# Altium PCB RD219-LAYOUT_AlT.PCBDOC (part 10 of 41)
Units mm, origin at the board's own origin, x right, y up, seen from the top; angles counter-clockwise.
Board outline 209.75 x 159.97 mm, 2 copper layers (TOP, BOTTOM), stack 0 mm thick; 398 components, 199 nets, 1469 pads, 0 vias.
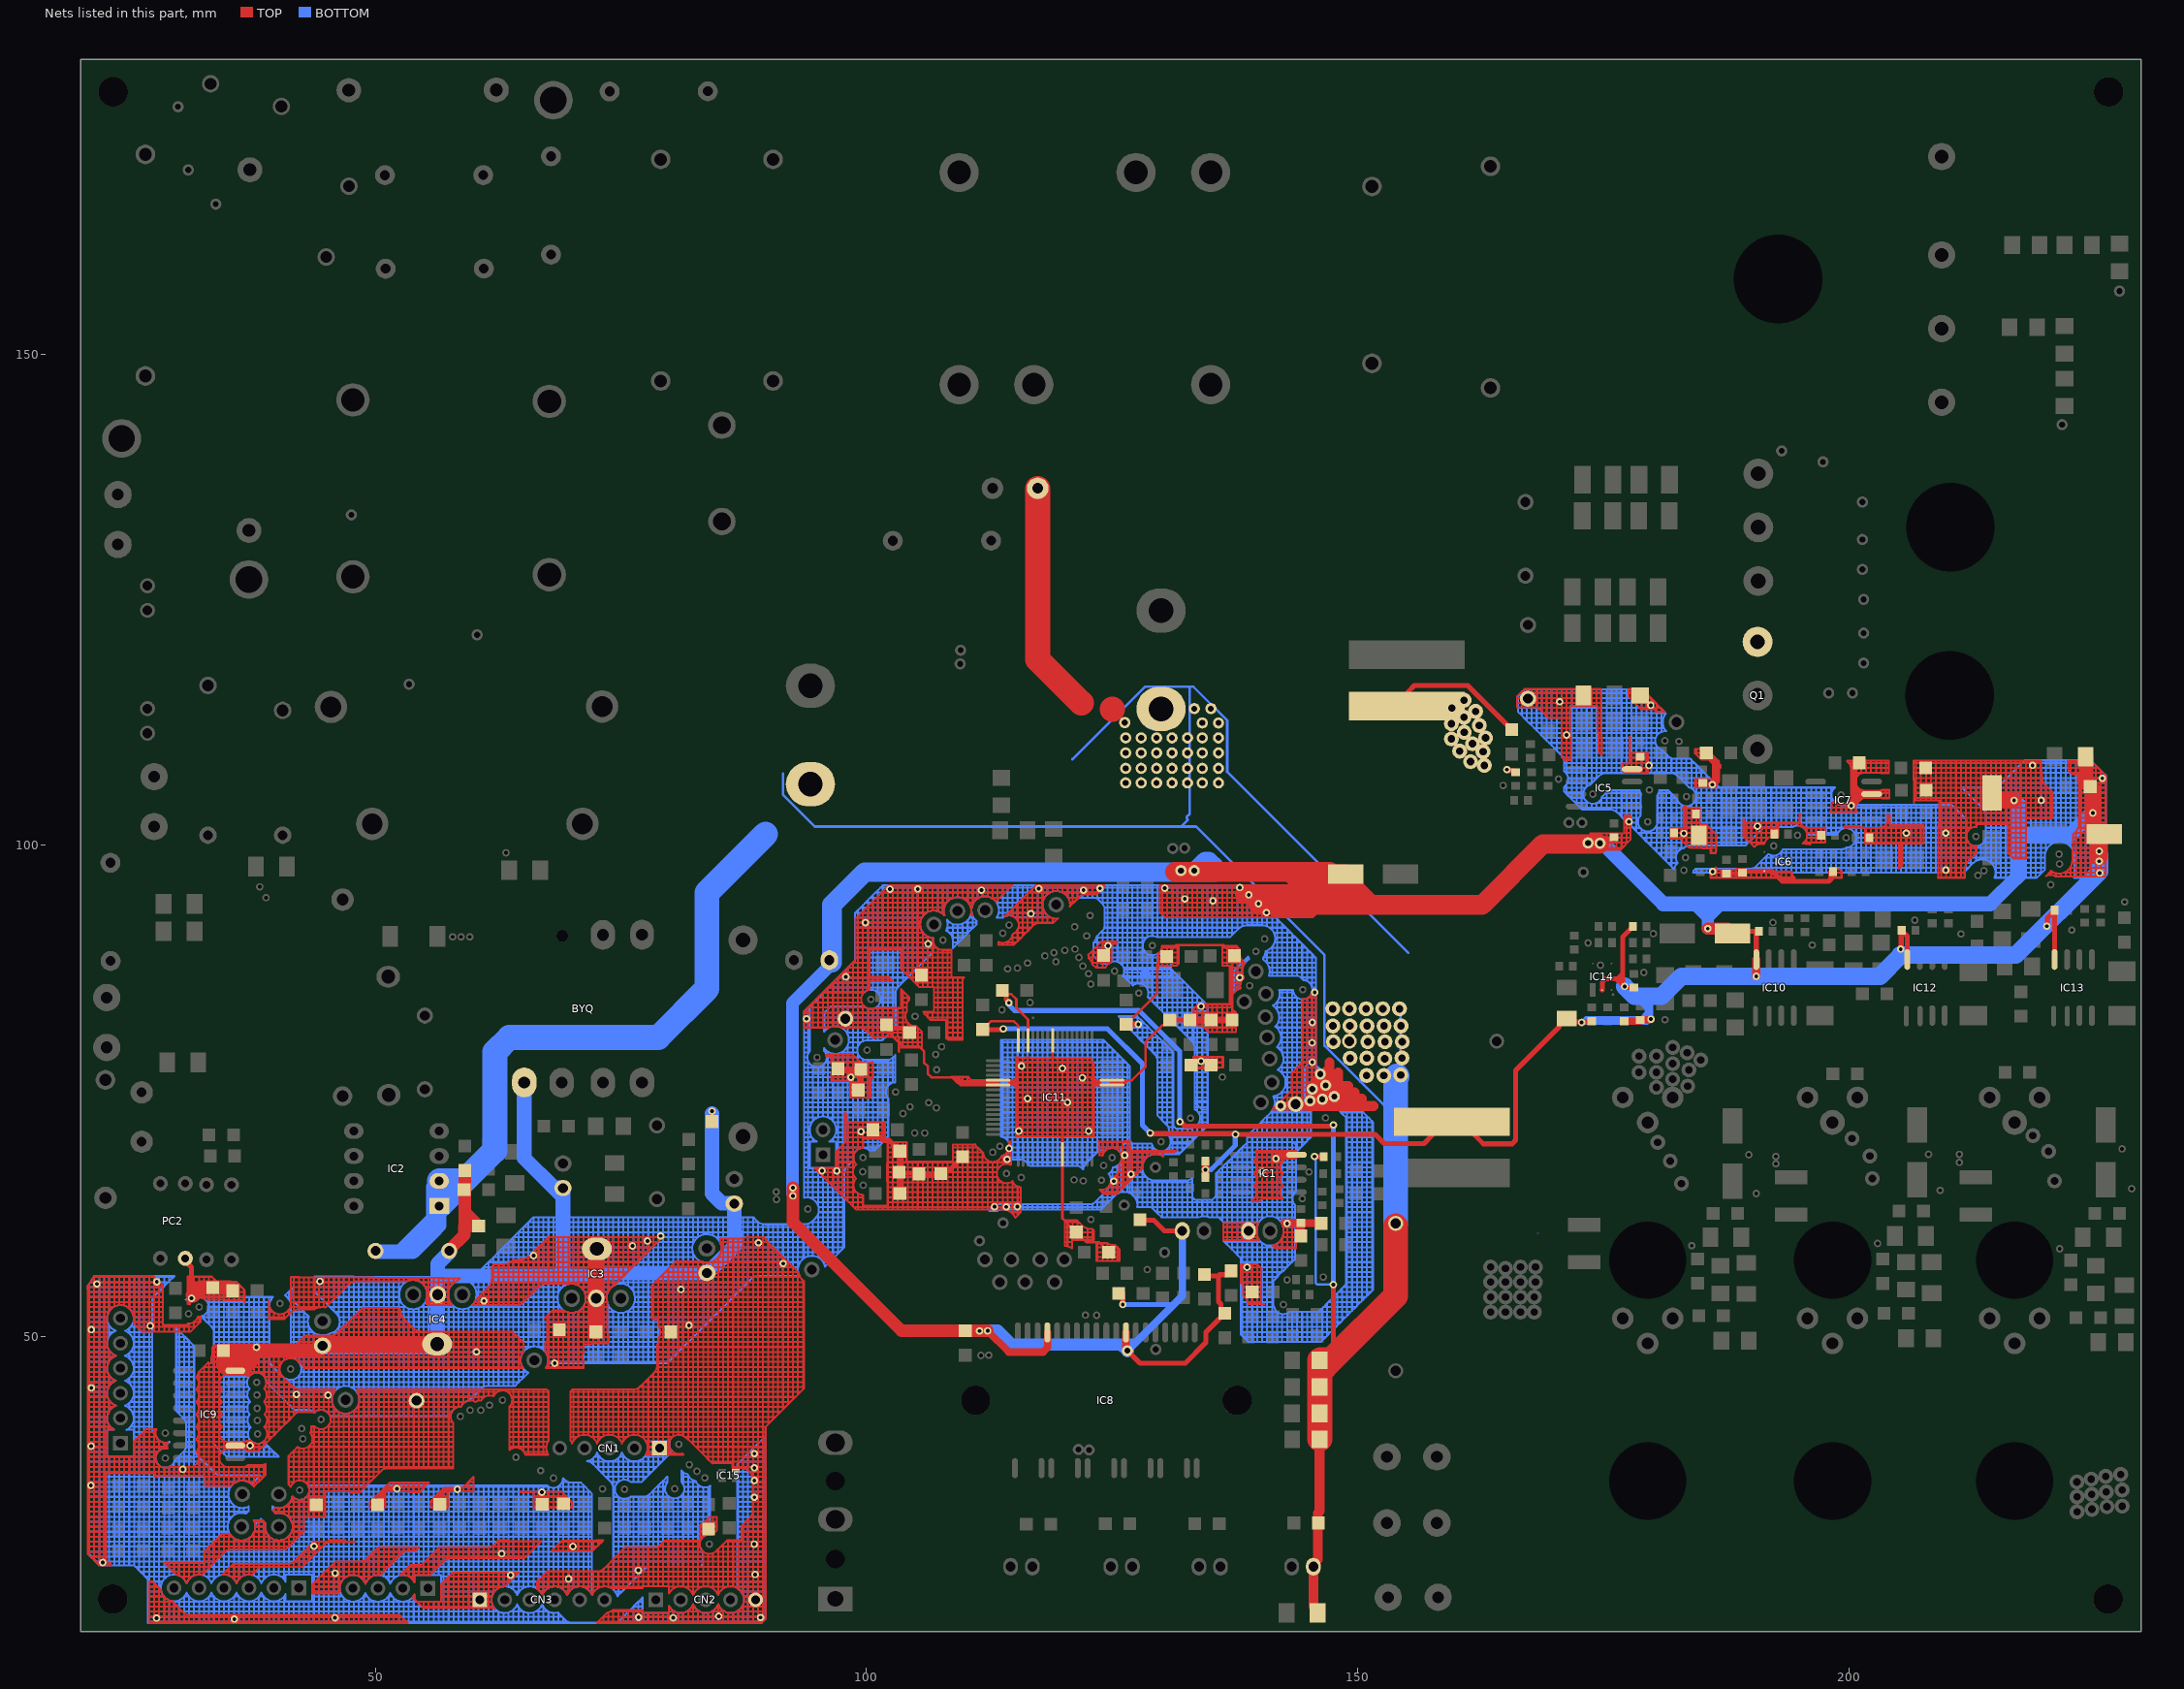
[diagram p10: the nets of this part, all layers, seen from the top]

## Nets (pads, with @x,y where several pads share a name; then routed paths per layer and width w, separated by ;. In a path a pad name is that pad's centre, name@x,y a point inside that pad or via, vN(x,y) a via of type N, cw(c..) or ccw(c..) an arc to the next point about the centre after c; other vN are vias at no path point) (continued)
GND: (continued)
  TOP w0.203: 78.293,51.756 78.318,51.732 78.801,51.732 ; 78.293,52.004 78.801,52.004 ; 78.293,52.004 78.293,52.512 ; 78.293,52.512 78.293,53.02 ; 78.293,52.512 78.801,52.512 ; 78.293,53.02 78.801,53.02 ; 78.293,53.02 78.293,53.528 ; 78.293,53.528 78.293,54.036 ; 78.293,53.528 78.801,53.528 ; 78.293,54.036 78.293,54.544 ; 78.293,54.036 78.801,54.036 ; 78.293,54.544 78.293,55.052 ; 78.293,54.544 78.801,54.544 ; 78.293,55.052 78.801,55.052 ; 78.293,55.052 78.293,55.363 ; 78.293,55.363 78.49,55.56 ; 78.293,59.186 78.293,59.624 ; 78.293,59.186 78.731,59.624 ; 78.293,59.624 78.293,60.132 ; 78.293,59.624 78.731,59.624 ; 78.293,60.132 pad.@78.801,60.132 ; 78.444,46.416 cw(c77.582,47.102) 78.361,46.323 ccw(c77.582,47.102) 78.444,46.416 ; 78.444,46.416 ccw(c77.582,47.102) 78.669,46.924 ; 78.444,46.416 ccw(c77.582,47.102) 78.669,46.924 ; 78.444,46.416 78.801,46.416 ; 78.454,28.542 ccw(c78.454,29.271) 78.801,28.631 ; 78.454,28.542 ccw(c78.454,29.271) 78.801,28.631 ; 78.49,55.56 78.801,55.56 ; 78.49,55.56 78.998,56.068 ; 78.669,46.924 ccw(c77.582,47.102) 78.683,47.102 ; 78.669,46.924 ccw(c77.582,47.102) 78.683,47.102 ; 78.669,46.924 78.801,46.924 ; 78.683,47.102 78.683,47.432 ; 78.683,47.432 78.801,47.432 ; 78.683,47.432 78.683,47.94 ; 78.683,47.94 78.801,47.94 ; 78.683,47.94 78.683,48.448 ; 78.683,48.448 78.801,48.448 ; 78.683,48.448 78.683,48.956 ; 78.683,48.956 78.801,48.956 ; 78.731,59.624 78.801,59.694 ; 78.801,20.889 78.801,21.016 ; 78.801,20.889 79.309,20.889 ; 78.801,21.016 78.801,21.524 ; 78.801,21.016 79.309,21.016 ; 78.801,21.524 78.801,21.889 ; 78.801,21.524 79.309,21.524 ; 78.801,21.889 79.309,21.889 ; 78.801,24.593 78.801,25.08 ; 78.801,24.593 79.309,24.593 ; 78.801,25.08 78.801,25.588 ; 78.801,25.08 79.309,25.08 ; 78.801,25.588 78.801,26.096 ; 78.801,25.588 79.309,25.588 ; 78.801,26.096 78.801,26.604 ; 78.801,26.096 79.309,26.096 ; 78.801,26.604 78.801,27.112 ; 78.801,26.604 79.309,26.604 ; 78.801,27.112 78.801,27.62 ; 78.801,27.112 79.309,27.112 ; 78.801,27.62 78.801,28.128 ; 78.801,27.62 79.309,27.62 ; 78.801,28.128 79.309,28.128 ; 78.801,28.128 78.801,28.631 ; 78.801,28.631 ccw(c78.454,29.271) 78.811,28.636 ; 78.801,28.631 ccw(c78.454,29.271) 78.811,28.636 ; CN1.1@78.801,38.004 CN1.1@78.801,38.288 ; CN1.1@78.801,38.004 CN1.1@79.309,38.004 ; CN1.1@78.801,38.288 CN1.1@79.309,38.288 ; CN1.1@78.801,38.288 CN1.1@78.801,38.796 ; CN1.1@78.801,38.796 CN1.1@78.801,39.304 ; CN1.1@78.801,38.796 CN1.1@79.309,38.796 ; CN1.1@78.801,39.304 78.801,39.812 ; CN1.1@78.801,39.304 CN1.1@79.309,39.304 ; 78.801,39.812 78.801,40.32 ; 78.801,39.812 79.309,39.812 ; 78.801,40.32 78.801,40.828 ; 78.801,40.32 79.309,40.32 ; 78.801,40.828 78.801,41.336 ; 78.801,40.828 79.309,40.828 ; 78.801,41.336 78.801,41.844 ; 78.801,41.336 79.309,41.336 ; 78.801,41.844 78.801,42.352 ; 78.801,41.844 79.309,41.844 ; 78.801,42.352 78.801,42.86 ; 78.801,42.352 79.309,42.352 ; 78.801,42.86 78.801,43.368 ; 78.801,42.86 79.309,42.86 ; 78.801,43.368 78.801,43.876 ; 78.801,43.368 79.309,43.368 ; 78.801,43.876 78.801,44.384 ; 78.801,43.876 79.309,43.876 ; 78.801,44.384 78.801,44.892 ; 78.801,44.384 79.309,44.384 ; 78.801,44.892 79.309,44.892 ; 78.801,44.892 78.801,45.4 ; 78.801,45.4 78.801,45.908 ; 78.801,45.4 79.309,45.4 ; 78.801,45.908 78.801,46.416 ; 78.801,45.908 79.309,45.908 ; 78.801,46.416 79.309,46.416 ; 78.801,46.416 78.801,46.924 ; 78.801,46.924 79.309,46.924 ; 78.801,46.924 78.801,47.432 ; 78.801,47.432 78.801,47.94 ; 78.801,47.432 79.309,47.432 ; 78.801,47.94 78.801,48.448 ; 78.801,47.94 79.309,47.94 ; 78.801,48.448 78.801,48.956 ; 78.801,48.448 79.309,48.448 ; 78.801,48.956 78.801,49.228 ; 78.801,48.956 79.309,48.956 ; 78.801,49.228 78.833,49.228 78.833,49.464 ; 78.801,51.732 78.801,52.004 ; 78.801,51.732 78.833,51.732 78.833,51.496 ; 78.801,52.004 79.309,52.004 ; 78.801,52.004 78.801,52.512 ; 78.801,52.512 78.801,53.02 ; 78.801,52.512 79.309,52.512 ; 78.801,53.02 79.309,53.02 ; 78.801,53.02 78.801,53.528 ; 78.801,53.528 78.801,54.036 ; 78.801,53.528 79.309,53.528 ; 78.801,54.036 78.801,54.544 ; 78.801,54.036 79.309,54.036 ; 78.801,54.544 78.801,55.052 ; 78.801,54.544 79.309,54.544 ; 78.801,55.052 79.309,55.052 ; 78.801,55.052 78.801,55.56 ; 78.801,55.56 79.309,55.56 ; 78.801,59.694 pad.@78.801,60.132 ; 78.811,28.636 ccw(c78.454,29.271) 78.969,28.756 ; 78.811,28.636 ccw(c78.454,29.271) 78.969,28.756 ; 78.811,28.636 79.309,28.636 ; 78.833,49.464 79.309,49.464 ; 78.833,49.464 78.833,49.813 ; 78.833,49.813 ccw(c77.658,50.48) 78.911,49.972 ; 78.833,51.147 cw(c77.658,50.48) 78.911,50.988 ; 78.833,51.147 78.833,51.496 ; 78.833,51.496 79.309,51.496 ; 78.911,49.972 ccw(c77.658,50.48) 79.01,50.48 ; 78.911,49.972 79.309,49.972 ; 78.911,50.988 cw(c77.658,50.48) 79.01,50.48 ; 78.911,50.988 79.309,50.988 ; 78.969,28.756 79.357,29.144 ; 78.998,56.068 79.309,56.379 ; 78.998,56.068 79.309,56.068 ; 79.01,50.48 79.309,50.48 ; 79.309,20.889 79.817,20.889 ; 79.309,20.889 79.309,21.016 ; 79.309,21.016 79.817,21.016 ; 79.309,21.016 79.309,21.524 ; 79.309,21.524 79.309,21.889 ; 79.309,21.524 79.817,21.524 ; 79.309,21.889 79.817,21.889 ; 79.309,24.593 79.309,25.08 ; 79.309,24.593 79.817,24.593 ; 79.309,25.08 79.309,25.588 ; 79.309,25.08 79.817,25.08 ; 79.309,25.588 79.309,26.096 ; 79.309,25.588 79.817,25.588 ; 79.309,26.096 79.309,26.604 ; 79.309,26.096 79.817,26.096 ; 79.309,26.604 79.309,27.112 ; 79.309,26.604 79.817,26.604 ; 79.309,27.112 79.309,27.62 ; 79.309,27.112 79.817,27.112 ; 79.309,27.62 79.309,28.128 ; 79.309,27.62 79.817,27.62 ; 79.309,28.128 79.309,28.636 ; 79.309,28.128 79.817,28.128 ; 79.309,28.636 79.817,28.636 ; CN1.1@79.309,38.004 79.817,38.004 ; CN1.1@79.309,38.004 CN1.1@79.309,38.288 ; CN1.1@79.309,38.288 79.817,38.288 ; CN1.1@79.309,38.288 CN1.1@79.309,38.796 ; CN1.1@79.309,38.796 CN1.1@79.309,39.304 ; CN1.1@79.309,38.796 79.817,38.796 ; CN1.1@79.309,39.304 79.309,39.812 ; CN1.1@79.309,39.304 79.817,39.304 ; 79.309,39.812 79.309,40.32 ; 79.309,39.812 79.817,39.812 ; 79.309,40.32 79.309,40.828 ; 79.309,40.32 79.817,40.32 ; 79.309,40.828 79.309,41.336 ; 79.309,40.828 79.817,40.828 ; 79.309,41.336 79.309,41.844 ; 79.309,41.336 79.817,41.336 ; 79.309,41.844 79.309,42.352 ; 79.309,41.844 79.817,41.844 ; 79.309,42.352 79.309,42.86 ; 79.309,42.352 79.817,42.352 ; 79.309,42.86 79.309,43.368 ; 79.309,42.86 79.817,42.86 ; 79.309,43.368 79.309,43.876 ; 79.309,43.368 79.817,43.368 ; 79.309,43.876 79.309,44.384 ; 79.309,43.876 79.817,43.876 ; 79.309,44.384 79.309,44.892 ; 79.309,44.384 79.817,44.384 ; 79.309,44.892 79.817,44.892 ; 79.309,44.892 79.309,45.4 ; 79.309,45.4 79.309,45.908 ; 79.309,45.4 79.817,45.4 ; 79.309,45.908 79.309,46.416 ; 79.309,45.908 79.817,45.908 ; 79.309,46.416 79.817,46.416 ; 79.309,46.416 79.309,46.924 ; 79.309,46.924 79.817,46.924 ; 79.309,46.924 79.309,47.432 ; 79.309,47.432 79.309,47.94 ; 79.309,47.432 79.817,47.432 ; 79.309,47.94 79.309,48.448 ; 79.309,47.94 79.817,47.94 ; 79.309,48.448 79.309,48.956 ; 79.309,48.448 79.817,48.448 ; 79.309,48.956 79.309,49.464 ; 79.309,48.956 79.817,48.956 ; 79.309,49.464 79.309,49.972 ; 79.309,49.464 79.817,49.464 ; 79.309,49.972 79.309,50.48 ; 79.309,49.972 C23.2@79.817,49.972 ; 79.309,50.48 79.309,50.988 ; 79.309,50.48 C23.2@79.817,50.48 ; 79.309,50.988 C23.2@79.817,50.988 ; 79.309,50.988 79.309,51.496 ; 79.309,51.496 79.309,52.004 ; 79.309,51.496 79.817,51.496 ; 79.309,52.004 79.309,52.512 ; 79.309,52.004 79.817,52.004 ; 79.309,52.512 79.309,53.02 ; 79.309,52.512 79.817,52.512 ; 79.309,53.02 79.309,53.528 ; 79.309,53.02 79.817,53.02 ; 79.309,53.528 79.309,54.036 ; 79.309,53.528 79.817,53.528 ; 79.309,54.036 79.309,54.544 ; 79.309,54.036 79.817,54.036 ; 79.309,54.544 79.309,55.052 ; 79.309,54.544 79.817,54.544 ; 79.309,55.052 79.309,55.56 ; 79.309,55.052 79.817,55.052 ; 79.309,55.56 79.309,56.068 ; 79.309,55.56 79.817,55.56 ; 79.309,56.068 79.309,56.379 ; 79.309,56.068 79.817,56.068 ; 79.309,56.379 79.506,56.576 ; 79.357,29.144 79.817,29.144 ; 79.357,29.144 79.455,29.242 79.817,29.242 ; 79.506,56.576 79.817,56.576 ; 79.506,56.576 79.817,56.887 ; 79.817,20.889 79.817,21.016 ; 79.817,20.889 80.325,20.889 ; 79.817,21.016 79.817,21.524 ; 79.817,21.016 80.325,21.016 ; 79.817,21.524 79.817,21.889 ; 79.817,21.524 pad.@80.325,21.524 ; 79.817,21.889 79.899,21.889 79.899,22.032 ; 79.817,24.593 79.817,25.08 ; 79.817,24.593 79.899,24.593 79.899,24.572 ; 79.817,25.08 79.817,25.588 ; 79.817,25.08 80.325,25.08 ; 79.817,25.588 79.817,26.096 ; 79.817,25.588 80.325,25.588 ; 79.817,26.096 79.817,26.604 ; 79.817,26.096 80.325,26.096 ; 79.817,26.604 79.817,27.112 ; 79.817,26.604 80.325,26.604 ; 79.817,27.112 79.817,27.62 ; 79.817,27.112 80.325,27.112 ; 79.817,27.62 79.817,28.128 ; 79.817,27.62 80.325,27.62 ; 79.817,28.128 79.817,28.636 ; 79.817,28.128 80.325,28.128 ; 79.817,28.636 79.817,29.144 ; 79.817,28.636 80.325,28.636 ; 79.817,29.144 80.325,29.144 ; 79.817,29.144 79.817,29.242 ; 79.817,29.242 80.325,29.242 ; 79.817,38.004 79.817,38.288 ; 79.817,38.004 80.325,38.004 ; 79.817,38.288 79.817,38.796 ; 79.817,38.288 80.275,38.288 ; 79.817,38.796 79.817,39.304 ; 79.817,38.796 79.946,38.796 ; 79.817,39.304 79.817,39.812 ; 79.817,39.304 79.945,39.304 ccw(c80.895,39.051) 79.912,39.051 ccw(c80.895,39.051) 79.946,38.796 ; 79.817,39.812 79.817,40.32 ; 79.817,39.812 80.274,39.812 ; 79.817,40.32 79.817,40.828 ; 79.817,40.32 80.325,40.32 ; 79.817,40.828 79.817,41.336 ; 79.817,40.828 80.325,40.828 ; 79.817,41.336 79.817,41.844 ; 79.817,41.336 80.325,41.336 ; 79.817,41.844 79.817,42.352 ; 79.817,41.844 80.325,41.844 ; 79.817,42.352 79.817,42.86 ; 79.817,42.352 80.325,42.352 ; 79.817,42.86 79.817,43.368 ; 79.817,42.86 80.325,42.86 ; 79.817,43.368 79.817,43.876 ; 79.817,43.368 80.325,43.368 ; 79.817,43.876 79.817,44.384 ; 79.817,43.876 80.325,43.876 ; 79.817,44.384 79.817,44.892 ; 79.817,44.384 80.325,44.384 ; 79.817,44.892 79.817,45.4 ; 79.817,44.892 80.325,44.892 ; 79.817,45.4 79.817,45.908 ; 79.817,45.4 80.325,45.4 ; 79.817,45.908 79.817,46.416 ; 79.817,45.908 80.325,45.908 ; 79.817,46.416 79.817,46.924 ; 79.817,46.416 80.325,46.416 ; 79.817,46.924 79.817,47.432 ; 79.817,46.924 80.325,46.924 ; 79.817,47.432 79.817,47.94 ; 79.817,47.432 80.325,47.432 ; 79.817,47.94 79.817,48.448 ; 79.817,47.94 80.325,47.94 ; 79.817,48.448 79.817,48.956 ; 79.817,48.448 80.325,48.448 ; 79.817,48.956 79.817,49.464 ; 79.817,48.956 80.325,48.956 ; 79.817,49.464 C23.2@79.817,49.972 ; 79.817,49.464 80.325,49.464 ; C23.2@79.817,49.972 C23.2@79.817,50.48 ; C23.2@79.817,49.972 C23.2@80.325,49.972 ; C23.2@79.817,50.48 C23.2@80.071,50.48 C23.2@80.325,50.48 ; C23.2@79.817,50.48 C23.2@79.817,50.988 ; C23.2@79.817,50.988 79.817,51.496 ; C23.2@79.817,50.988 C23.2@80.325,50.988 ; 79.817,51.496 79.817,52.004 ; 79.817,51.496 80.325,51.496 ; 79.817,52.004 79.817,52.512 ; 79.817,52.004 80.325,52.004 ; 79.817,52.512 79.817,53.02 ; 79.817,52.512 80.325,52.512 ; 79.817,53.02 79.817,53.528 ; 79.817,53.02 80.325,53.02 ; 79.817,53.528 79.817,54.036 ; 79.817,53.528 80.325,53.528 ; 79.817,54.036 79.817,54.544 ; 79.817,54.036 80.325,54.036 ; 79.817,54.544 79.817,55.052 ; 79.817,54.544 80.325,54.544 ; 79.817,55.052 79.817,55.56 ; 79.817,55.052 80.325,55.052 ; 79.817,55.56 79.817,56.068 ; 79.817,55.56 80.325,55.56 ; 79.817,56.068 79.817,56.576 ; 79.817,56.068 80.325,56.068 ; 79.817,56.576 79.817,56.887 ; 79.817,56.576 80.325,56.576 ; 79.817,56.887 80.014,57.084 ; 79.899,22.032 80.325,22.032 ; 79.899,22.032 79.899,22.597 ; 79.899,22.597 ccw(c81.087,23.241) 80.325,22.125 ; 79.899,24.064 79.899,24.572 ; 79.899,24.064 80.015,24.064 ; 79.899,24.572 80.325,24.572 ; 79.946,38.796 ccw(c80.895,39.051) 80.275,38.288 ; 80.014,57.084 80.325,57.084 ; 80.014,57.084 80.325,57.395 ; 80.015,24.064 cw(c81.087,23.241) 80.325,24.357 ; 80.274,39.812 cw(c80.895,39.051) 80.325,39.851 ; 80.275,38.288 ccw(c80.895,39.051) 80.276,38.287 ccw(c80.895,39.051) 80.325,38.25 ; 80.325,20.889 80.325,21.016 ; 80.325,20.889 80.833,20.889 ; 80.325,21.016 80.833,21.016 ; 80.325,21.016 pad.@80.325,21.524 ; pad.@80.325,21.524 80.325,22.032 ; pad.@80.325,21.524 80.833,21.524 ; 80.325,22.032 80.483,22.032 ; 80.325,22.032 80.325,22.125 ; 80.325,22.125 ccw(c81.087,23.241) 80.483,22.032 ; 80.325,24.357 cw(c81.087,23.241) 80.331,24.362 cw(c81.087,23.241) 80.833,24.569 ; 80.325,24.357 80.325,24.572 ; 80.325,24.572 80.833,24.572 ; 80.325,24.572 80.325,25.08 ; 80.325,25.08 80.833,25.08 ; 80.325,25.08 80.325,25.588 ; 80.325,25.588 80.325,26.096 ; 80.325,25.588 80.833,25.588 ; 80.325,26.096 80.833,26.096 ; 80.325,26.096 80.325,26.604 ; 80.325,26.604 80.325,27.112 ; 80.325,26.604 80.833,26.604 ; 80.325,27.112 80.325,27.62 ; 80.325,27.112 80.833,27.112 ; 80.325,27.62 80.325,28.128 ; 80.325,27.62 80.833,27.62 ; 80.325,28.128 80.325,28.636 ; 80.325,28.128 80.833,28.128 ; 80.325,28.636 80.833,28.636 ; 80.325,28.636 80.325,29.144 ; 80.325,29.144 80.833,29.144 ; 80.325,29.144 80.325,29.242 ; 80.325,29.242 80.833,29.242 ; 80.325,38.004 80.325,38.25 ; 80.325,39.851 cw(c80.895,39.051) 80.826,40.031 cw(c80.895,39.051) 80.833,40.031 ; 80.325,39.851 80.325,40.32 ; 80.325,40.32 80.325,40.828 ; 80.325,40.32 80.833,40.32 ; 80.325,40.828 80.325,41.336 ; 80.325,40.828 80.833,40.828 ; 80.325,41.336 80.325,41.844 ; 80.325,41.336 80.833,41.336 ; 80.325,41.844 80.325,42.352 ; 80.325,41.844 80.833,41.844 ; 80.325,42.352 80.325,42.86 ; 80.325,42.352 80.833,42.352 ; 80.325,42.86 80.325,43.368 ; 80.325,42.86 80.833,42.86 ; 80.325,43.368 80.325,43.876 ; 80.325,43.368 80.833,43.368 ; 80.325,43.876 80.325,44.384 ; 80.325,43.876 80.833,43.876 ; 80.325,44.384 80.325,44.892 ; 80.325,44.384 80.833,44.384 ; 80.325,44.892 80.325,45.4 ; 80.325,44.892 80.833,44.892 ; 80.325,45.4 80.325,45.908 ; 80.325,45.4 80.833,45.4 ; 80.325,45.908 80.325,46.416 ; 80.325,45.908 80.833,45.908 ; 80.325,46.416 80.325,46.924 ; 80.325,46.416 80.833,46.416 ; 80.325,46.924 80.325,47.432 ; 80.325,46.924 80.833,46.924 ; 80.325,47.432 80.325,47.94 ; 80.325,47.432 80.833,47.432 ; 80.325,47.94 80.325,48.448 ; 80.325,47.94 80.833,47.94 ; 80.325,48.448 80.325,48.956 ; 80.325,48.448 80.833,48.448 ; 80.325,48.956 80.325,49.464 ; 80.325,48.956 80.833,48.956 ; 80.325,49.464 C23.2@80.325,49.972 ; 80.325,49.464 80.833,49.464 ; C23.2@80.325,49.972 80.833,49.972 ; C23.2@80.325,49.972 C23.2@80.325,50.48 ; C23.2@80.325,50.48 80.833,50.48 ; C23.2@80.325,50.48 C23.2@80.325,50.988 ; C23.2@80.325,50.988 80.325,51.496 ; C23.2@80.325,50.988 80.833,50.988 ; 80.325,51.496 80.325,52.004 ; 80.325,51.496 80.833,51.496 ; 80.325,52.004 80.325,52.512 ; 80.325,52.004 80.833,52.004 ; 80.325,52.512 80.325,53.02 ; 80.325,52.512 80.833,52.512 ; 80.325,53.02 80.325,53.528 ; 80.325,53.02 80.833,53.02 ; 80.325,53.528 80.325,54.036 ; 80.325,53.528 80.833,53.528 ; 80.325,54.036 80.325,54.544 ; 80.325,54.036 80.833,54.036 ; 80.325,54.544 80.325,55.052 ; 80.325,54.544 80.833,54.544 ; 80.325,55.052 80.325,55.56 ; 80.325,55.052 pad.@80.833,55.052 ; 80.325,55.56 80.325,56.068 ; 80.325,55.56 80.833,55.56 ; 80.325,56.068 80.325,56.576 ; 80.325,56.068 80.833,56.068 ; 80.325,56.576 80.325,57.084 ; 80.325,56.576 80.833,56.576 ; 80.325,57.084 80.325,57.395 ; 80.325,57.084 80.833,57.084 ; 80.325,57.395 80.522,57.592 ; 80.483,22.032 ccw(c81.087,23.241) 80.829,21.914 ccw(c81.087,23.241) 80.833,21.914 ; 80.522,57.592 80.567,57.637 80.833,57.637 ; 80.522,57.592 80.833,57.592 ; 80.833,20.889 80.833,21.016 ; 80.833,20.889 81.341,20.889 ; 80.833,21.016 80.833,21.524 ; 80.833,21.016 81.341,21.016 ; 80.833,21.524 81.341,21.524 ; 80.833,21.524 80.833,21.913 ; 80.833,21.914 ccw(c81.087,23.241) 81.341,21.913 ; 80.833,24.569 cw(c81.087,23.241) 80.852,24.572 ; 80.833,24.569 80.833,24.572 ; 80.833,24.572 80.833,25.08 ; 80.833,24.572 80.852,24.572 ; 80.833,25.08 80.833,25.588 ; 80.833,25.08 81.341,25.08 ; 80.833,25.588 80.833,26.096 ; 80.833,25.588 81.341,25.588 ; 80.833,26.096 80.833,26.604 ; 80.833,26.096 81.341,26.096 ; 80.833,26.604 80.833,27.112 ; 80.833,26.604 81.341,26.604 ; 80.833,27.112 80.833,27.62 ; 80.833,27.112 81.341,27.112 ; 80.833,27.62 80.833,28.128 ; 80.833,27.62 81.341,27.62 ; 80.833,28.128 80.833,28.636 ; 80.833,28.128 81.341,28.128 ; 80.833,28.636 80.833,29.144 ; 80.833,28.636 81.341,28.636 ; 80.833,29.144 80.833,29.242 ; 80.833,29.144 81.341,29.144 ; 80.833,40.031 cw(c80.895,39.051) 81.341,39.926 ; 80.833,40.031 80.833,40.32 ; 80.833,40.32 80.833,40.828 ; 80.833,40.32 81.341,40.32 ; 80.833,40.828 80.833,41.336 ; 80.833,40.828 81.341,40.828 ; 80.833,41.336 80.833,41.844 ; 80.833,41.336 81.341,41.336 ; 80.833,41.844 80.833,42.352 ; 80.833,41.844 81.341,41.844 ; 80.833,42.352 80.833,42.86 ; 80.833,42.352 81.341,42.352 ; 80.833,42.86 80.833,43.368 ; 80.833,42.86 81.341,42.86 ; 80.833,43.368 80.833,43.876 ; 80.833,43.368 81.341,43.368 ; 80.833,43.876 80.833,44.384 ; 80.833,43.876 81.341,43.876 ; 80.833,44.384 80.833,44.892 ; 80.833,44.384 81.341,44.384 ; 80.833,44.892 80.833,45.4 ; 80.833,44.892 81.341,44.892 ; 80.833,45.4 80.833,45.908 ; 80.833,45.4 81.341,45.4 ; 80.833,45.908 80.833,46.416 ; 80.833,45.908 81.341,45.908 ; 80.833,46.416 80.833,46.924 ; 80.833,46.416 81.341,46.416 ; 80.833,46.924 80.833,47.432 ; 80.833,46.924 81.341,46.924 ; 80.833,47.432 80.833,47.94 ; 80.833,47.432 81.341,47.432 ; 80.833,47.94 80.833,48.448 ; 80.833,47.94 81.341,47.94 ; 80.833,48.448 80.833,48.956 ; 80.833,48.448 81.341,48.448 ; 80.833,48.956 80.833,49.464 ; 80.833,48.956 81.341,48.956 ; 80.833,49.464 80.833,49.972 ; 80.833,49.464 81.341,49.464 ; 80.833,49.972 80.833,50.48 ; 80.833,49.972 81.341,49.972 ; 80.833,50.48 80.833,50.988 ; 80.833,50.48 81.341,50.48 ; 80.833,50.988 80.833,51.496 ; 80.833,50.988 81.341,50.988 ; 80.833,51.496 80.833,52.004 ; 80.833,51.496 81.341,51.496 ; 80.833,52.004 80.833,52.512 ; 80.833,52.004 81.341,52.004 ; 80.833,52.512 80.833,53.02 ; 80.833,52.512 81.341,52.512 ; 80.833,53.02 80.833,53.528 ; 80.833,53.02 81.341,53.02 ; 80.833,53.528 80.833,54.036 ; 80.833,53.528 81.341,53.528 ; 80.833,54.036 80.833,54.544 ; 80.833,54.036 81.341,54.036 ; 80.833,54.544 pad.@80.833,55.052 ; 80.833,54.544 pad.@81.341,54.544 ; pad.@80.833,55.052 80.833,55.56 ; pad.@80.833,55.052 pad.@81.341,55.052 ; 80.833,55.56 80.833,56.068 ; 80.833,55.56 81.341,55.56 ; 80.833,56.068 80.833,56.576 ; 80.833,56.068 81.341,56.068 ; 80.833,56.576 80.833,57.084 ; 80.833,56.576 81.341,56.576 ; 80.833,57.084 80.833,57.592 ; 80.833,57.084 81.341,57.084 ; 80.833,57.592 80.833,57.637 ; 80.833,57.592 81.341,57.592 ; 80.833,57.637 81.341,57.637 ; 80.852,24.572 cw(c81.087,23.241) 81.322,24.572 ; 81.322,24.572 cw(c81.087,23.241) 81.341,24.569 ; 81.322,24.572 81.341,24.572 ; 81.341,20.889 81.341,21.016 ; 81.341,20.889 81.849,20.889 ; 81.341,21.016 81.341,21.524 ; 81.341,21.016 81.849,21.016 ; 81.341,21.524 81.849,21.524 ; 81.341,21.524 81.341,21.913 ; 81.341,21.913 ccw(c81.087,23.241) 81.345,21.914 ccw(c81.087,23.241) 81.691,22.032 ; 81.341,24.569 cw(c81.087,23.241) 81.345,24.568 cw(c81.087,23.241) 81.843,24.362 cw(c81.087,23.241) 81.849,24.357 ; 81.341,24.569 81.341,24.572 ; 81.341,24.572 81.849,24.572 ; 81.341,24.572 81.341,25.08 ; 81.341,25.08 81.341,25.588 ; 81.341,25.08 81.849,25.08 ; 81.341,25.588 81.341,26.096 ; 81.341,25.588 81.849,25.588 ; 81.341,26.096 81.341,26.604 ; 81.341,26.096 81.849,26.096 ; 81.341,26.604 81.341,27.112 ; 81.341,26.604 81.849,26.604 ; 81.341,27.112 81.341,27.62 ; 81.341,27.112 81.849,27.112 ; 81.341,27.62 81.341,28.128 ; 81.341,27.62 81.849,27.62 ; 81.341,28.128 81.341,28.636 ; 81.341,28.128 81.849,28.128 ; 81.341,28.636 81.341,29.144 ; 81.341,28.636 81.849,28.636 ; 81.341,29.144 81.341,29.256 ; 81.341,29.144 81.849,29.144 ; 81.341,29.256 81.849,29.256 ; 81.341,39.926 cw(c80.895,39.051) 81.516,39.812 ; 81.341,39.926 81.341,40.32 ; 81.341,40.32 81.341,40.828 ; 81.341,40.32 81.849,40.32 ; 81.341,40.828 81.341,41.336 ; 81.341,40.828 81.849,40.828 ; 81.341,41.336 81.341,41.844 ; 81.341,41.336 81.849,41.336 ; 81.341,41.844 81.341,42.352 ; 81.341,41.844 81.849,41.844 ; 81.341,42.352 81.341,42.86 ; 81.341,42.352 81.849,42.352 ; 81.341,42.86 81.341,43.368 ; 81.341,42.86 81.849,42.86 ; 81.341,43.368 81.341,43.876 ; 81.341,43.368 81.849,43.368 ; 81.341,43.876 81.341,44.384 ; 81.341,43.876 81.849,43.876 ; 81.341,44.384 81.849,44.384 ; 81.341,44.384 81.341,44.892 ; 81.341,44.892 81.849,44.892 ; 81.341,44.892 81.341,45.4 ; 81.341,45.4 81.341,45.908 ; 81.341,45.4 81.849,45.4 ; 81.341,45.908 81.341,46.416 ; 81.341,45.908 81.849,45.908 ; 81.341,46.416 81.849,46.416 ; 81.341,46.416 81.341,46.924 ; 81.341,46.924 81.849,46.924 ; 81.341,46.924 81.341,47.432 ; 81.341,47.432 81.341,47.94 ; 81.341,47.432 81.849,47.432 ; 81.341,47.94 81.341,48.448 ; 81.341,47.94 81.849,47.94 ; 81.341,48.448 81.341,48.956 ; 81.341,48.448 81.849,48.448 ; 81.341,48.956 81.341,49.464 ; 81.341,48.956 81.849,48.956 ; 81.341,49.464 81.341,49.972 ; 81.341,49.464 81.849,49.464 ; 81.341,49.972 81.849,49.972 ; 81.341,49.972 81.341,50.48 ; 81.341,50.48 81.341,50.988 ; 81.341,50.48 81.849,50.48 ; 81.341,50.988 pad.@81.849,50.988 ; 81.341,50.988 81.341,51.496 ; 81.341,51.496 81.341,52.004 ; 81.341,51.496 pad.@81.849,51.496 ; 81.341,52.004 81.849,52.004 ; 81.341,52.004 81.341,52.512 ; 81.341,52.512 81.341,53.02 ; 81.341,52.512 81.849,52.512 ; 81.341,53.02 81.849,53.02 ; 81.341,53.02 81.341,53.528 ; 81.341,53.528 81.341,54.036 ; 81.341,53.528 81.849,53.528 ; 81.341,54.036 pad.@81.341,54.544 ; 81.341,54.036 81.849,54.036 ; pad.@81.341,54.544 81.849,54.544 ; pad.@81.341,54.544 pad.@81.341,55.052 ; pad.@81.341,55.052 81.849,55.052 ; pad.@81.341,55.052 81.341,55.56 ; 81.341,55.56 81.849,55.56 ; 81.341,55.56 81.341,56.068 ; 81.341,56.068 81.341,56.576 ; 81.341,56.068 81.849,56.068 ; 81.341,56.576 81.849,56.576 ; 81.341,56.576 81.341,57.084 ; 81.341,57.084 81.341,57.592 ; 81.341,57.084 81.849,57.084 ; 81.341,57.592 81.849,57.592 ; 81.341,57.592 81.341,57.637 ; 81.341,57.637 81.849,57.637 ; 81.516,39.812 cw(c80.895,39.051) 81.656,39.672 ; 81.516,39.812 81.849,39.812 ; 81.656,39.672 cw(c81.402,38.989) 81.849,39.564 ; 81.656,39.672 ccw(c81.402,38.989) 81.652,39.673 cw(c81.402,38.989) 81.656,39.672 ; 81.656,39.672 cw(c81.402,38.989) 81.849,39.564 ; 81.691,22.032 ccw(c81.087,23.241) 81.843,22.12 ccw(c81.087,23.241) 81.849,22.125 ; 81.691,22.032 81.849,22.032 ; 81.849,20.889 82.357,20.889 ; 81.849,20.889 81.849,21.016 ; 81.849,21.016 82.357,21.016 ; 81.849,21.016 81.849,21.524 ; 81.849,21.524 81.849,22.032 ; 81.849,21.524 82.357,21.524 ; 81.849,22.032 82.357,22.032 ; 81.849,22.032 81.849,22.125 ; 81.849,24.357 81.849,24.572 ; 81.849,24.572 81.849,25.08 ; 81.849,24.572 82.357,24.572 ; 81.849,25.08 82.357,25.08 ; 81.849,25.08 81.849,25.588 ; 81.849,25.588 81.849,26.096 ; 81.849,25.588 82.357,25.588 ; 81.849,26.096 82.357,26.096 ; 81.849,26.096 81.849,26.604 ; 81.849,26.604 81.849,27.112 ; 81.849,26.604 82.357,26.604 ; 81.849,27.112 81.849,27.62 ; 81.849,27.112 82.357,27.112 ; 81.849,27.62 81.849,28.128 ; 81.849,27.62 82.357,27.62 ; 81.849,28.128 81.849,28.636 ; 81.849,28.128 82.357,28.128 ; 81.849,28.636 82.357,28.636 ; 81.849,28.636 81.849,29.144 ; 81.849,29.144 82.357,29.144 ; 81.849,29.144 81.849,29.256 ; 81.849,29.256 82.357,29.256 ; 81.849,39.564 cw(c81.402,38.989) 81.918,39.504 ; 81.849,39.564 cw(c81.402,38.989) 81.918,39.504 ; 81.849,39.564 81.849,39.812 ; 81.849,39.812 81.849,40.32 ; 81.849,39.812 82.357,39.812 ; 81.849,40.32 81.849,40.828 ; 81.849,40.32 82.357,40.32 ; 81.849,40.828 81.849,41.336 ; 81.849,40.828 82.357,40.828 ; 81.849,41.336 81.849,41.844 ; 81.849,41.336 82.357,41.336 ; 81.849,41.844 81.849,42.352 ; 81.849,41.844 82.357,41.844 ; 81.849,42.352 81.849,42.86 ; 81.849,42.352 82.357,42.352 ; 81.849,42.86 81.849,43.368 ; 81.849,42.86 82.357,42.86 ; 81.849,43.368 81.849,43.876 ; 81.849,43.368 82.357,43.368 ; 81.849,43.876 81.849,44.384 ; 81.849,43.876 82.357,43.876 ; 81.849,44.384 82.357,44.384 ; 81.849,44.384 81.849,44.892 ; 81.849,44.892 82.357,44.892 ; 81.849,44.892 81.849,45.4 ; 81.849,45.4 81.849,45.908 ; 81.849,45.4 82.357,45.4 ; 81.849,45.908 81.849,46.416 ; 81.849,45.908 82.357,45.908 ; 81.849,46.416 82.357,46.416 ; 81.849,46.416 81.849,46.924 ; 81.849,46.924 82.357,46.924 ; 81.849,46.924 81.849,47.432 ; 81.849,47.432 81.849,47.94 ; 81.849,47.432 82.357,47.432 ; 81.849,47.94 81.849,48.448 ; 81.849,47.94 82.357,47.94 ; 81.849,48.448 81.849,48.956 ; 81.849,48.448 82.357,48.448 ; 81.849,48.956 81.849,49.464 ; 81.849,48.956 82.357,48.956 ; 81.849,49.464 81.849,49.972 ; 81.849,49.464 82.357,49.464 ; 81.849,49.972 81.849,50.48 ; 81.849,49.972 82.357,49.972 ; 81.849,50.48 pad.@81.849,50.988 ; 81.849,50.48 82.357,50.48 ; pad.@81.849,50.988 82.357,50.988 ; pad.@81.849,50.988 pad.@81.849,51.496 ; pad.@81.849,51.496 81.849,52.004 ; pad.@81.849,51.496 82.357,51.496 ; 81.849,52.004 81.849,52.512 ; 81.849,52.004 82.357,52.004 ; 81.849,52.512 81.849,53.02 ; 81.849,52.512 82.357,52.512 ; 81.849,53.02 82.357,53.02 ; 81.849,53.02 81.849,53.528 ; 81.849,53.528 81.849,54.036 ; 81.849,53.528 82.357,53.528 ; 81.849,54.036 81.849,54.544 ; 81.849,54.036 82.357,54.036 ; 81.849,54.544 81.849,55.052 ; 81.849,54.544 82.357,54.544 ; 81.849,55.052 82.357,55.052 ; 81.849,55.052 81.849,55.56 ; 81.849,55.56 82.357,55.56 ; 81.849,55.56 81.849,56.068 ; 81.849,56.068 81.849,56.576 ; 81.849,56.068 82.357,56.068 ; 81.849,56.576 82.357,56.576 ; 81.849,56.576 81.849,57.084 ; 81.849,57.084 81.849,57.592 ; 81.849,57.084 82.357,57.084 ; 81.849,57.592 82.357,57.592 ; 81.849,57.592 81.849,57.637 ; 81.849,57.637 82.357,57.637 ; 81.918,39.504 82.117,39.304 ; 82.117,39.304 82.357,39.304 ; 82.117,39.304 82.357,39.064 ; 82.357,20.889 82.357,21.016 ; 82.357,20.889 82.865,20.889 ; 82.357,21.016 82.865,21.016 ; 82.357,21.016 82.357,21.524 ; 82.357,21.524 82.357,22.032 ; 82.357,21.524 82.865,21.524 ; 82.357,22.032 82.865,22.032 ; 82.357,22.032 82.357,22.54 ; 82.357,22.54 82.357,22.778 ; 82.357,22.54 82.471,22.54 ; 82.357,22.778 ccw(c83.627,23.241) 82.468,22.545 ccw(c83.627,23.241) 82.471,22.54 ; 82.357,24.064 82.357,24.572 ; 82.357,24.064 82.555,24.064 ; 82.357,24.572 82.357,25.08 ; 82.357,24.572 82.865,24.572 ; 82.357,25.08 82.357,25.588 ; 82.357,25.08 82.865,25.08 ; 82.357,25.588 82.357,26.096 ; 82.357,25.588 82.865,25.588 ; 82.357,26.096 82.357,26.604 ; 82.357,26.096 82.865,26.096 ; 82.357,26.604 82.357,27.112 ; 82.357,26.604 82.865,26.604 ; 82.357,27.112 82.357,27.62 ; 82.357,27.112 82.865,27.112 ; 82.357,27.62 82.357,28.128 ; 82.357,27.62 82.865,27.62 ; 82.357,28.128 82.357,28.636 ; 82.357,28.128 82.865,28.128 ; 82.357,28.636 82.357,29.144 ; 82.357,28.636 82.865,28.636 ; 82.357,29.144 82.865,29.144 ; 82.357,29.144 82.357,29.256 ; 82.357,29.256 82.865,29.256 ; 82.357,39.064 82.357,39.304 ; 82.357,39.064 82.625,38.796 ; 82.357,39.304 82.357,39.812 ; 82.357,39.304 82.865,39.304 ; 82.357,39.812 82.357,40.32 ; 82.357,39.812 82.865,39.812 ; 82.357,40.32 82.357,40.828 ; 82.357,40.32 82.865,40.32 ; 82.357,40.828 82.357,41.336 ; 82.357,40.828 82.865,40.828 ; 82.357,41.336 82.357,41.844 ; 82.357,41.336 82.865,41.336 ; 82.357,41.844 82.357,42.352 ; 82.357,41.844 82.865,41.844 ; 82.357,42.352 82.357,42.86 ; 82.357,42.352 82.865,42.352 ; 82.357,42.86 82.357,43.368 ; 82.357,42.86 82.865,42.86 ; 82.357,43.368 82.357,43.876 ; 82.357,43.368 82.865,43.368 ; 82.357,43.876 82.357,44.384 ; 82.357,43.876 82.865,43.876 ; 82.357,44.384 82.357,44.892 ; 82.357,44.384 82.865,44.384 ; 82.357,44.892 82.357,45.4 ; 82.357,44.892 82.865,44.892 ; 82.357,45.4 82.357,45.908 ; 82.357,45.4 82.865,45.4 ; 82.357,45.908 82.357,46.416 ; 82.357,45.908 82.865,45.908 ; 82.357,46.416 82.357,46.924 ; 82.357,46.416 82.865,46.416 ; 82.357,46.924 82.357,47.432 ; 82.357,46.924 82.865,46.924 ; 82.357,47.432 82.357,47.94 ; 82.357,47.432 82.865,47.432 ; 82.357,47.94 82.357,48.448 ; 82.357,47.94 82.865,47.94 ; 82.357,48.448 82.357,48.956 ; 82.357,48.448 82.865,48.448 ; 82.357,48.956 82.357,49.464 ; 82.357,48.956 82.865,48.956 ; 82.357,49.464 82.357,49.972 ; 82.357,49.464 82.865,49.464 ; 82.357,49.972 82.357,50.48 ; 82.357,49.972 82.865,49.972 ; 82.357,50.48 82.357,50.988 ; 82.357,50.48 82.865,50.48 ; 82.357,50.988 82.865,50.988 ; 82.357,50.988 82.357,51.496 ; 82.357,51.496 82.357,52.004 ; 82.357,51.496 82.865,51.496 ; 82.357,52.004 82.357,52.512 ; 82.357,52.004 82.865,52.004 ; 82.357,52.512 82.357,53.02 ; 82.357,52.512 82.865,52.512 ; 82.357,53.02 82.357,53.528 ; 82.357,53.02 82.865,53.02 ; 82.357,53.528 82.357,54.036 ; 82.357,53.528 82.865,53.528 ; 82.357,54.036 82.357,54.544 ; 82.357,54.036 82.865,54.036 ; 82.357,54.544 82.357,55.052 ; 82.357,54.544 82.865,54.544 ; 82.357,55.052 82.357,55.56 ; 82.357,55.052 82.865,55.052 ; 82.357,55.56 82.357,56.068 ; 82.357,55.56 82.865,55.56 ; 82.357,56.068 82.357,56.576 ; 82.357,56.068 82.865,56.068 ; 82.357,56.576 82.357,57.084 ; 82.357,56.576 82.865,56.576 ; 82.357,57.084 82.357,57.592 ; 82.357,57.084 82.865,57.084 ; 82.357,57.592 82.357,57.637 ; 82.357,57.592 82.865,57.592 ; 82.357,57.637 82.865,57.637 ; 82.471,22.54 ccw(c83.627,23.241) 82.865,22.125 ; 82.555,24.064 cw(c83.627,23.241) 82.562,24.073 cw(c83.627,23.241) 82.865,24.357 ; 82.625,38.796 82.865,38.796 ; 82.625,38.796 82.865,38.556 ; 82.865,20.889 82.865,21.016 ; 82.865,20.889 83.373,20.889 ; 82.865,21.016 82.865,21.524 ; 82.865,21.016 83.373,21.016 ; 82.865,21.524 82.865,22.032 ; 82.865,21.524 83.373,21.524 ; 82.865,22.032 83.023,22.032 ; 82.865,22.032 82.865,22.125 ; 82.865,22.125 ccw(c83.627,23.241) 83.013,22.037 ccw(c83.627,23.241) 83.023,22.032 ; 82.865,24.357 cw(c83.627,23.241) 83.373,24.569 ; 82.865,24.357 82.865,24.572 ; 82.865,24.572 83.373,24.572 ; 82.865,24.572 82.865,25.08 ; 82.865,25.08 82.865,25.588 ; 82.865,25.08 83.373,25.08 ; 82.865,25.588 82.865,26.096 ; 82.865,25.588 83.373,25.588 ; 82.865,26.096 82.865,26.604 ; 82.865,26.096 83.373,26.096 ; 82.865,26.604 82.865,27.112 ; 82.865,26.604 83.373,26.604 ; 82.865,27.112 82.865,27.62 ; 82.865,27.112 83.373,27.112 ; 82.865,27.62 82.865,28.128 ; 82.865,27.62 83.373,27.62 ; 82.865,28.128 82.865,28.636 ; 82.865,28.128 83.373,28.128 ; 82.865,28.636 82.865,29.144 ; 82.865,28.636 83.059,28.636 ; 82.865,29.144 82.865,29.256 ; 82.865,29.144 83.059,29.144 ; 82.865,29.256 83.065,29.256 83.065,29.652 ; 82.865,38.556 82.865,38.796 ; 82.865,38.556 83.133,38.288 ; 82.865,38.796 82.865,39.304 ; 82.865,38.796 83.373,38.796 ; 82.865,39.304 82.865,39.812 ; 82.865,39.304 83.373,39.304 ; 82.865,39.812 83.373,39.812 ; 82.865,39.812 82.865,40.32 ; 82.865,40.32 82.865,40.828 ; 82.865,40.32 83.373,40.32 ; 82.865,40.828 82.865,41.336 ; 82.865,40.828 83.373,40.828 ; 82.865,41.336 82.865,41.844 ; 82.865,41.336 83.373,41.336 ; 82.865,41.844 82.865,42.352 ; 82.865,41.844 83.373,41.844 ; 82.865,42.352 82.865,42.86 ; 82.865,42.352 83.373,42.352 ; 82.865,42.86 82.865,43.368 ; 82.865,42.86 83.373,42.86 ; 82.865,43.368 82.865,43.876 ; 82.865,43.368 83.373,43.368 ; 82.865,43.876 82.865,44.384 ; 82.865,43.876 83.373,43.876 ; 82.865,44.384 83.373,44.384 ; 82.865,44.384 82.865,44.892 ; 82.865,44.892 83.373,44.892 ; 82.865,44.892 82.865,45.4 ; 82.865,45.4 82.865,45.908 ; 82.865,45.4 83.373,45.4 ; 82.865,45.908 82.865,46.416 ; 82.865,45.908 83.373,45.908 ; 82.865,46.416 83.373,46.416 ; 82.865,46.416 82.865,46.924 ; 82.865,46.924 83.373,46.924 ; 82.865,46.924 82.865,47.432 ; 82.865,47.432 82.865,47.94 ; 82.865,47.432 83.373,47.432 ; 82.865,47.94 82.865,48.448 ; 82.865,47.94 83.373,47.94 ; 82.865,48.448 82.865,48.956 ; 82.865,48.448 83.373,48.448 ; 82.865,48.956 82.865,49.464 ; 82.865,48.956 83.373,48.956 ; 82.865,49.464 82.865,49.972 ; 82.865,49.464 83.373,49.464 ; 82.865,49.972 83.373,49.972 ; 82.865,49.972 82.865,50.48 ; 82.865,50.48 82.865,50.988 ; 82.865,50.48 83.373,50.48 ; 82.865,50.988 83.373,50.988 ; 82.865,50.988 82.865,51.496 ; 82.865,51.496 82.865,52.004 ; 82.865,51.496 83.373,51.496 ; 82.865,52.004 83.373,52.004 ; 82.865,52.004 82.865,52.512 ; 82.865,52.512 82.865,53.02 ; 82.865,52.512 83.373,52.512 ; 82.865,53.02 83.373,53.02 ; 82.865,53.02 82.865,53.528 ; 82.865,53.528 82.865,54.036 ; 82.865,53.528 83.373,53.528 ; 82.865,54.036 82.865,54.544 ; 82.865,54.036 83.373,54.036 ; 82.865,54.544 82.865,55.052 ; 82.865,54.544 83.373,54.544 ; 82.865,55.052 83.373,55.052 ; 82.865,55.052 82.865,55.56 ; 82.865,55.56 83.373,55.56 ; 82.865,55.56 82.865,56.068 ; 82.865,56.068 EC5.2@83.373,56.068 ; 82.865,56.068 82.865,56.576 ; 82.865,56.576 EC5.2@83.373,56.576 ; 82.865,56.576 82.865,57.084 ; 82.865,57.084 82.865,57.592 ; 82.865,57.084 EC5.2@83.373,57.084 ; 82.865,57.592 83.373,57.592 ; 82.865,57.592 82.865,57.637 ; 82.865,57.637 83.232,57.637 ; 83.023,22.032 ccw(c83.627,23.241) 83.369,21.914 ccw(c83.627,23.241) 83.373,21.914 ; 83.059,28.636 ccw(c84.008,28.89) 83.373,28.14 ; 83.059,28.636 cw(c84.008,28.89) 83.059,29.144 ; 83.059,29.144 cw(c84.008,28.89) 83.373,29.64 ; 83.065,29.652 83.373,29.652 ; 83.065,29.652 83.065,30.16 ; 83.065,30.16 C110.2@83.373,30.16 ; 83.065,30.16 83.065,30.668 ; 83.065,30.668 C110.2@83.373,30.668 ; 83.133,38.288 83.373,38.048 ; 83.133,38.288 83.373,38.288 ; 83.232,57.637 ccw(c83.691,58.989) 83.373,57.598 ; 83.373,20.889 83.373,21.016 ; 83.373,20.889 83.881,20.889 ; 83.373,21.016 83.373,21.524 ; 83.373,21.016 83.881,21.016 ; 83.373,21.524 83.881,21.524 ; 83.373,21.524 83.373,21.913 ; 83.373,21.914 ccw(c83.627,23.241) 83.881,21.913 ; 83.373,24.569 cw(c83.627,23.241) 83.392,24.572 ; 83.373,24.569 83.373,24.572 ; 83.373,24.572 83.373,25.08 ; 83.373,24.572 83.392,24.572 ; 83.373,25.08 83.881,25.08 ; 83.373,25.08 83.373,25.588 ; 83.373,25.588 83.373,26.096 ; 83.373,25.588 83.881,25.588 ; 83.373,26.096 83.881,26.096 ; 83.373,26.096 83.373,26.604 ; 83.373,26.604 83.373,27.112 ; 83.373,26.604 83.881,26.604 ; 83.373,27.112 83.373,27.62 ; 83.373,27.112 83.881,27.112 ; 83.373,27.62 83.373,28.128 ; 83.373,27.62 83.881,27.62 ; 83.373,28.128 83.388,28.128 ; 83.373,28.128 83.373,28.14 ; 83.373,28.14 ccw(c84.008,28.89) 83.376,28.137 ccw(c84.008,28.89) 83.388,28.128 ; 83.373,29.64 cw(c84.008,28.89) 83.388,29.652 ; 83.373,29.64 83.373,29.652 ; 83.373,29.652 C110.2@83.373,30.16 ; 83.373,29.652 83.388,29.652 ; C110.2@83.373,30.16 C110.2@83.881,30.16 ; C110.2@83.373,30.16 C110.2@83.373,30.668 ; C110.2@83.373,30.668 C110.2@83.881,30.668 ; C110.2@83.373,30.668 C110.2@83.373,31.014 ; C110.2@83.373,31.014 cw(c82.921,31.74) 83.07,30.898 ccw(c82.921,31.74) C110.2@83.373,31.014 ; C110.2@83.373,31.014 ccw(c82.921,31.74) 83.526,31.135 ; C110.2@83.373,31.014 ccw(c82.921,31.74) 83.526,31.135 ; 83.373,38.048 83.641,37.78 ; 83.373,38.048 83.373,38.288 ; 83.373,38.288 83.373,38.796 ; 83.373,38.288 83.881,38.288 ; 83.373,38.796 83.373,39.304 ; 83.373,38.796 83.881,38.796 ; 83.373,39.304 83.373,39.812 ; 83.373,39.304 83.881,39.304 ; 83.373,39.812 83.881,39.812 ; 83.373,39.812 83.373,40.32 ; 83.373,40.32 83.373,40.828 ; 83.373,40.32 83.881,40.32 ; 83.373,40.828 83.373,41.336 ; 83.373,40.828 83.881,40.828 ; 83.373,41.336 83.373,41.844 ; 83.373,41.336 83.881,41.336 ; 83.373,41.844 83.373,42.352 ; 83.373,41.844 83.881,41.844 ; 83.373,42.352 83.373,42.86 ; 83.373,42.352 83.881,42.352 ; 83.373,42.86 83.373,43.368 ; 83.373,42.86 83.881,42.86 ; 83.373,43.368 83.373,43.876 ; 83.373,43.368 83.881,43.368 ; 83.373,43.876 83.373,44.384 ; 83.373,43.876 83.881,43.876 ; 83.373,44.384 83.373,44.892 ; 83.373,44.384 83.881,44.384 ; 83.373,44.892 83.373,45.4 ; 83.373,44.892 83.881,44.892 ; 83.373,45.4 83.373,45.908 ; 83.373,45.4 83.881,45.4 ; 83.373,45.908 83.373,46.416 ; 83.373,45.908 83.881,45.908 ; 83.373,46.416 83.881,46.416 ; 83.373,46.416 83.373,46.924 ; 83.373,46.924 83.881,46.924 ; 83.373,46.924 83.373,47.432 ; 83.373,47.432 83.373,47.94 ; 83.373,47.432 83.881,47.432 ; 83.373,47.94 83.373,48.448 ; 83.373,47.94 83.881,47.94 ; 83.373,48.448 83.373,48.956 ; 83.373,48.448 83.881,48.448 ; 83.373,48.956 83.373,49.464 ; 83.373,48.956 83.881,48.956 ; 83.373,49.464 83.373,49.972 ; 83.373,49.464 83.881,49.464 ; 83.373,49.972 83.373,50.48 ; 83.373,49.972 83.881,49.972 ; 83.373,50.48 83.373,50.988 ; 83.373,50.48 83.881,50.48 ; 83.373,50.988 83.881,50.988 ; 83.373,50.988 83.373,51.496 ; 83.373,51.496 83.373,52.004 ; 83.373,51.496 83.881,51.496 ; 83.373,52.004 83.373,52.512 ; 83.373,52.004 83.881,52.004 ; 83.373,52.512 83.373,53.02 ; 83.373,52.512 83.881,52.512 ; 83.373,53.02 83.373,53.528 ; 83.373,53.02 83.881,53.02 ; 83.373,53.528 83.373,54.036 ; 83.373,53.528 83.881,53.528 ; 83.373,54.036 83.373,54.544 ; 83.373,54.036 83.881,54.036 ; 83.373,54.544 83.373,55.052 ; 83.373,54.544 83.881,54.544 ; 83.373,55.052 83.373,55.56 ; 83.373,55.052 83.881,55.052 ; 83.373,55.56 83.881,55.56 ; 83.373,55.56 EC5.2@83.373,56.068 ; EC5.2@83.373,56.068 EC5.2@83.373,56.576 ; EC5.2@83.373,56.068 EC5.2@83.881,56.068 ; EC5.2@83.373,56.576 EC5.2@83.373,57.084 ; EC5.2@83.373,56.576 EC5.2@83.881,56.576 ; EC5.2@83.373,57.084 83.373,57.592 ; EC5.2@83.373,57.084 EC5.2@83.881,57.084 ; 83.373,57.592 83.373,57.598 ; 83.373,57.592 83.399,57.592 ; 83.373,57.598 ccw(c83.691,58.989) 83.399,57.592 ; 83.388,28.128 ccw(c84.008,28.89) 83.881,27.916 ; 83.388,29.652 cw(c84.008,28.89) C110.2@83.881,29.864 ; 83.392,24.572 cw(c83.627,23.241) 83.862,24.572 ; 83.399,57.592 ccw(c83.691,58.989) 83.691,57.562 83.818,57.562 ccw(c83.818,58.989) 83.881,57.563 ; 83.526,31.135 83.567,31.176 ; 83.567,31.176 83.881,31.176 ; 83.567,31.176 83.881,31.49 ; 83.641,37.78 83.881,37.54 ; 83.641,37.78 83.881,37.78 ; 83.862,24.572 cw(c83.627,23.241) 83.881,24.569 ; 83.862,24.572 83.881,24.572 ; 83.881,20.889 83.881,21.016 ; 83.881,20.889 84.389,20.889 ; 83.881,21.016 83.881,21.524 ; 83.881,21.016 84.389,21.016 ; 83.881,21.524 84.389,21.524 ; 83.881,21.524 83.881,21.913 ; 83.881,21.913 ccw(c83.627,23.241) 83.885,21.914 ccw(c83.627,23.241) 84.231,22.032 ; 83.881,24.569 cw(c83.627,23.241) 84.383,24.362 cw(c83.627,23.241) 84.389,24.357 ; 83.881,24.569 83.881,24.572 ; 83.881,24.572 84.389,24.572 ; 83.881,24.572 83.881,25.08 ; 83.881,25.08 83.881,25.588 ; 83.881,25.08 84.389,25.08 ; 83.881,25.588 83.881,26.096 ; 83.881,25.588 84.389,25.588 ; 83.881,26.096 83.881,26.604 ; 83.881,26.096 84.389,26.096 ; 83.881,26.604 83.881,27.112 ; 83.881,26.604 84.389,26.604 ; 83.881,27.112 83.881,27.62 ; 83.881,27.112 84.389,27.112 ; 83.881,27.62 84.389,27.62 ; 83.881,27.62 83.881,27.916 ; 83.881,27.916 ccw(c84.008,28.89) 84.389,27.984 ; C110.2@83.881,29.864 C110.2@83.881,30.16 ; C110.2@83.881,30.16 C110.2@83.881,30.668 ; C110.2@83.881,30.16 C110.2@84.389,30.16 ; C110.2@83.881,30.668 83.881,31.176 ; C110.2@83.881,30.668 C110.2@84.389,30.668 ; 83.881,31.176 83.881,31.49 ; 83.881,31.176 84.389,31.176 ; 83.881,31.49 84.056,31.665 84.389,31.665 ; 83.881,37.54 84.149,37.272 ; 83.881,37.54 83.881,37.78 ; 83.881,37.78 83.881,38.288 ; 83.881,37.78 84.389,37.78 ; 83.881,38.288 83.881,38.796 ; 83.881,38.288 84.389,38.288 ; 83.881,38.796 83.881,39.304 ; 83.881,38.796 84.389,38.796 ; 83.881,39.304 83.881,39.812 ; 83.881,39.304 84.389,39.304 ; 83.881,39.812 83.881,40.32 ; 83.881,39.812 84.389,39.812 ; 83.881,40.32 83.881,40.828 ; 83.881,40.32 84.389,40.32 ; 83.881,40.828 83.881,41.336 ; 83.881,40.828 84.389,40.828 ; 83.881,41.336 83.881,41.844 ; 83.881,41.336 84.389,41.336 ; 83.881,41.844 83.881,42.352 ; 83.881,41.844 84.389,41.844 ; 83.881,42.352 83.881,42.86 ; 83.881,42.352 84.389,42.352 ; 83.881,42.86 83.881,43.368 ; 83.881,42.86 84.389,42.86 ; 83.881,43.368 83.881,43.876 ; 83.881,43.368 84.389,43.368 ; 83.881,43.876 83.881,44.384 ; 83.881,43.876 84.389,43.876 ; 83.881,44.384 83.881,44.892 ; 83.881,44.384 84.389,44.384 ; 83.881,44.892 83.881,45.4 ; 83.881,44.892 84.389,44.892 ; 83.881,45.4 83.881,45.908 ; 83.881,45.4 84.389,45.4 ; 83.881,45.908 83.881,46.416 ; 83.881,45.908 84.389,45.908 ; 83.881,46.416 83.881,46.924 ; 83.881,46.416 84.389,46.416 ; 83.881,46.924 83.881,47.432 ; 83.881,46.924 84.389,46.924 ; 83.881,47.432 83.881,47.94 ; 83.881,47.432 84.389,47.432 ; 83.881,47.94 83.881,48.448 ; 83.881,47.94 84.389,47.94 ; 83.881,48.448 83.881,48.956 ; 83.881,48.448 84.389,48.448 ; 83.881,48.956 83.881,49.464 ; 83.881,48.956 84.389,48.956 ; 83.881,49.464 83.881,49.972 ; 83.881,49.464 84.389,49.464 ; 83.881,49.972 83.881,50.48 ; 83.881,49.972 84.389,49.972 ; 83.881,50.48 83.881,50.988 ; 83.881,50.48 84.389,50.48 ; 83.881,50.988 83.881,51.496 ; 83.881,50.988 84.389,50.988 ; 83.881,51.496 83.881,52.004 ; 83.881,51.496 84.389,51.496 ; 83.881,52.004 83.881,52.512 ; 83.881,52.004 84.389,52.004 ; 83.881,52.512 83.881,53.02 ; 83.881,52.512 84.389,52.512 ; 83.881,53.02 83.881,53.528 ; 83.881,53.02 84.389,53.02 ; 83.881,53.528 83.881,54.036 ; 83.881,53.528 84.389,53.528 ; 83.881,54.036 83.881,54.544 ; 83.881,54.036 84.389,54.036 ; 83.881,54.544 83.881,55.052 ; 83.881,54.544 84.389,54.544 ; 83.881,55.052 83.881,55.56 ; 83.881,55.052 84.389,55.052 ; 83.881,55.56 EC5.2@83.881,56.068 ; 83.881,55.56 84.389,55.56 ; EC5.2@83.881,56.068 EC5.2@84.389,56.068 ; EC5.2@83.881,56.068 EC5.2@83.881,56.576 ; EC5.2@83.881,56.576 EC5.2@83.881,57.084 ; EC5.2@83.881,56.576 EC5.2@84.389,56.576 ; EC5.2@83.881,57.084 84.389,57.084 ; EC5.2@83.881,57.084 83.881,57.563 ; 83.881,57.563 ccw(c83.818,58.989) 84.109,57.592 ; 84.109,57.592 ccw(c83.818,58.989) 84.114,57.593 ccw(c83.818,58.989) 84.389,57.681 ; 84.109,57.592 84.389,57.592 ; 84.149,37.272 84.389,37.272 ; 84.231,22.032 ccw(c83.627,23.241) 84.383,22.12 ccw(c83.627,23.241) 84.389,22.125 ; 84.231,22.032 84.389,22.032 ; 84.389,20.889 84.897,20.889 ; 84.389,20.889 84.389,21.016 ; 84.389,21.016 84.897,21.016 ; 84.389,21.016 84.389,21.524 ; 84.389,21.524 84.389,22.032 ; 84.389,21.524 pad.@84.897,21.524 ; 84.389,22.032 84.897,22.032 ; 84.389,22.032 84.389,22.125 ; 84.389,24.357 84.389,24.572 ; 84.389,24.572 84.897,24.572 ; 84.389,24.572 84.389,25.08 ; 84.389,25.08 84.897,25.08 ; 84.389,25.08 84.389,25.588 ; 84.389,25.588 84.389,26.096 ; 84.389,25.588 84.897,25.588 ; 84.389,26.096 84.897,26.096 ; 84.389,26.096 84.389,26.604 ; 84.389,26.604 84.389,27.112 ; 84.389,26.604 84.897,26.604 ; 84.389,27.112 84.389,27.62 ; 84.389,27.112 84.897,27.112 ; 84.389,27.62 84.897,27.62 ; 84.389,27.62 84.389,27.984 ; 84.389,27.984 ccw(c84.008,28.89) 84.392,27.986 ccw(c84.008,28.89) 84.626,28.126 ccw(c84.008,28.89) 84.628,28.128 ; C110.2@84.389,30.16 C110.2@84.389,30.668 ; C110.2@84.389,30.668 84.389,31.176 ; C110.2@84.389,30.668 84.775,30.668 ; 84.389,31.176 84.389,31.665 ; 84.389,31.176 84.775,31.176 ; 84.389,31.665 84.775,31.665 84.775,31.176 ; 84.389,37.152 84.897,37.152 ; 84.389,37.152 84.389,37.272 ; 84.389,37.272 84.389,37.78 ; 84.389,37.272 84.897,37.272 ; 84.389,37.78 84.389,38.288 ; 84.389,37.78 84.897,37.78 ; 84.389,38.288 84.389,38.796 ; 84.389,38.288 84.897,38.288 ; 84.389,38.796 84.389,39.304 ; 84.389,38.796 84.897,38.796 ; 84.389,39.304 84.389,39.812 ; 84.389,39.304 84.897,39.304 ; 84.389,39.812 84.389,40.32 ; 84.389,39.812 84.897,39.812 ; 84.389,40.32 84.389,40.828 ; 84.389,40.32 84.897,40.32 ; 84.389,40.828 84.389,41.336 ; 84.389,40.828 84.897,40.828 ; 84.389,41.336 84.389,41.844 ; 84.389,41.336 84.897,41.336 ; 84.389,41.844 84.389,42.352 ; 84.389,41.844 84.897,41.844 ; 84.389,42.352 84.389,42.86 ; 84.389,42.352 84.897,42.352 ; 84.389,42.86 84.389,43.368 ; 84.389,42.86 84.897,42.86 ; 84.389,43.368 84.389,43.876 ; 84.389,43.368 84.897,43.368 ; 84.389,43.876 84.389,44.384 ; 84.389,43.876 84.897,43.876 ; 84.389,44.384 84.389,44.892 ; 84.389,44.384 84.897,44.384 ; 84.389,44.892 84.389,45.4 ; 84.389,44.892 84.897,44.892 ; 84.389,45.4 84.389,45.908 ; 84.389,45.4 84.897,45.4 ; 84.389,45.908 84.389,46.416 ; 84.389,45.908 84.897,45.908 ; 84.389,46.416 84.389,46.924 ; 84.389,46.416 84.897,46.416 ; 84.389,46.924 84.389,47.432 ; 84.389,46.924 84.897,46.924 ; 84.389,47.432 84.389,47.94 ; 84.389,47.432 84.897,47.432 ; 84.389,47.94 84.389,48.448 ; 84.389,47.94 84.897,47.94 ; 84.389,48.448 84.389,48.956 ; 84.389,48.448 84.897,48.448 ; 84.389,48.956 84.389,49.464 ; 84.389,48.956 84.897,48.956 ; 84.389,49.464 84.389,49.972 ; 84.389,49.464 84.897,49.464 ; 84.389,49.972 84.389,50.48 ; 84.389,49.972 84.897,49.972 ; 84.389,50.48 84.389,50.988 ; 84.389,50.48 84.897,50.48 ; 84.389,50.988 84.389,51.496 ; 84.389,50.988 84.897,50.988 ; 84.389,51.496 84.389,52.004 ; 84.389,51.496 84.897,51.496 ; 84.389,52.004 84.389,52.512 ; 84.389,52.004 84.897,52.004 ; 84.389,52.512 84.389,53.02 ; 84.389,52.512 84.897,52.512 ; 84.389,53.02 84.389,53.528 ; 84.389,53.02 84.897,53.02 ; 84.389,53.528 84.389,54.036 ; 84.389,53.528 84.897,53.528 ; 84.389,54.036 84.389,54.544 ; 84.389,54.036 84.897,54.036 ; 84.389,54.544 84.389,55.052 ; 84.389,54.544 84.897,54.544 ; 84.389,55.052 84.389,55.56 ; 84.389,55.052 84.897,55.052 ; 84.389,55.56 EC5.2@84.389,56.068 ; 84.389,55.56 84.897,55.56 ; EC5.2@84.389,56.068 84.897,56.068 ; EC5.2@84.389,56.068 EC5.2@84.389,56.576 ; EC5.2@84.389,56.576 84.389,57.084 ; EC5.2@84.389,56.576 84.897,56.576 ; 84.389,57.084 84.389,57.592 ; 84.389,57.084 84.897,57.084 ; 84.389,57.592 84.897,57.592 ; 84.389,57.592 84.389,57.681 ; 84.389,57.681 ccw(c83.818,58.989) 84.897,58.056 ; 84.628,28.128 84.897,28.128 ; 84.775,30.668 84.775,31.176 ; 84.897,20.889 84.897,21.016 ; 84.897,20.889 85.405,20.889 ; 84.897,21.016 pad.@84.897,21.524 ; 84.897,21.016 85.405,21.016 ; pad.@84.897,21.524 84.897,22.032 ; pad.@84.897,21.524 85.405,21.524 ; 84.897,22.032 84.897,22.54 ; 84.897,22.032 85.405,22.032 ; 84.897,22.54 84.897,22.778 ; 84.897,22.54 85.011,22.54 ; 84.897,22.778 ccw(c86.167,23.241) 85.008,22.545 ccw(c86.167,23.241) 85.011,22.54 ; 84.897,24.064 84.897,24.572 ; 84.897,24.064 85.095,24.064 ; 84.897,24.572 84.897,25.08 ; 84.897,24.572 85.405,24.572 ; 84.897,25.08 84.897,25.588 ; 84.897,25.08 85.405,25.08 ; 84.897,25.588 84.897,26.096 ; 84.897,25.588 85.405,25.588 ; 84.897,26.096 84.897,26.604 ; 84.897,26.096 85.405,26.096 ; 84.897,26.604 84.897,27.112 ; 84.897,26.604 85.405,26.604 ; 84.897,27.112 84.897,27.62 ; 84.897,27.112 85.405,27.112 ; 84.897,27.62 84.897,28.128 ; 84.897,27.62 85.405,27.62 ; 84.897,28.128 85.405,28.128 ; 84.897,28.128 84.897,28.385 ; 84.897,28.385 cw(c84.483,28.984) 84.825,28.341 ccw(c84.483,28.984) 84.897,28.385 ; 84.897,28.385 ccw(c84.483,28.984) 84.999,28.469 ; 84.897,28.385 ccw(c84.483,28.984) 84.999,28.469 ; 84.897,37.152 84.897,37.272 ; 84.897,37.152 85.405,37.152 ; 84.897,37.272 84.897,37.78 ; 84.897,37.272 85.405,37.272 ; 84.897,37.78 84.897,38.288 ; 84.897,37.78 85.405,37.78 ; 84.897,38.288 84.897,38.796 ; 84.897,38.288 85.405,38.288 ; 84.897,38.796 84.897,39.304 ; 84.897,38.796 85.405,38.796 ; 84.897,39.304 84.897,39.812 ; 84.897,39.304 85.405,39.304 ; 84.897,39.812 84.897,40.32 ; 84.897,39.812 85.405,39.812 ; 84.897,40.32 84.897,40.828 ; 84.897,40.32 85.405,40.32 ; 84.897,40.828 84.897,41.336 ; 84.897,40.828 85.405,40.828 ; 84.897,41.336 84.897,41.844 ; 84.897,41.336 85.405,41.336 ; 84.897,41.844 84.897,42.352 ; 84.897,41.844 85.405,41.844 ; 84.897,42.352 84.897,42.86 ; 84.897,42.352 85.405,42.352 ; 84.897,42.86 84.897,43.368 ; 84.897,42.86 85.405,42.86 ; 84.897,43.368 84.897,43.876 ; 84.897,43.368 85.405,43.368 ; 84.897,43.876 84.897,44.384 ; 84.897,43.876 85.405,43.876 ; 84.897,44.384 84.897,44.892 ; 84.897,44.384 85.405,44.384 ; 84.897,44.892 84.897,45.4 ; 84.897,44.892 85.405,44.892 ; 84.897,45.4 84.897,45.908 ; 84.897,45.4 85.405,45.4 ; 84.897,45.908 84.897,46.416 ; 84.897,45.908 85.405,45.908 ; 84.897,46.416 84.897,46.924 ; 84.897,46.416 85.405,46.416 ; 84.897,46.924 84.897,47.432 ; 84.897,46.924 85.405,46.924 ; 84.897,47.432 84.897,47.94 ; 84.897,47.432 85.405,47.432 ; 84.897,47.94 84.897,48.448 ; 84.897,47.94 85.405,47.94 ; 84.897,48.448 84.897,48.956 ; 84.897,48.448 85.405,48.448 ; 84.897,48.956 84.897,49.464 ; 84.897,48.956 85.405,48.956 ; 84.897,49.464 84.897,49.972 ; 84.897,49.464 85.405,49.464 ; 84.897,49.972 84.897,50.48 ; 84.897,49.972 85.405,49.972 ; 84.897,50.48 84.897,50.988 ; 84.897,50.48 85.405,50.48 ; 84.897,50.988 84.897,51.496 ; 84.897,50.988 85.405,50.988 ; 84.897,51.496 84.897,52.004 ; 84.897,51.496 85.405,51.496 ; 84.897,52.004 84.897,52.512 ; 84.897,52.004 85.405,52.004 ; 84.897,52.512 84.897,53.02 ; 84.897,52.512 85.405,52.512 ; 84.897,53.02 84.897,53.528 ; 84.897,53.02 85.405,53.02 ; 84.897,53.528 84.897,54.036 ; 84.897,53.528 85.405,53.528 ; 84.897,54.036 84.897,54.544 ; 84.897,54.036 85.405,54.036 ; 84.897,54.544 84.897,55.052 ; 84.897,54.544 85.405,54.544 ; 84.897,55.052 84.897,55.56 ; 84.897,55.052 85.405,55.052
